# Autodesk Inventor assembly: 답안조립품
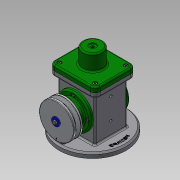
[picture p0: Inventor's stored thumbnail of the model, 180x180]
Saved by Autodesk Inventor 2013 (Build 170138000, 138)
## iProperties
Created: 2019-08
Part Number: 답안조립품
Document SubType Name: Assembly
Designer: Administrator
Author: Administrator
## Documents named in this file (17)
- C:\Documents and Settings\Administrator\바탕 화면\490804V1012\답안조립품.iam
- C:\Documents and Settings\Administrator\바탕 화면\490804V1012\본체.ipt
- C:\Documents and Settings\Administrator\바탕 화면\490804V1012\편심축.ipt
- C:\Documents and Settings\Administrator\바탕 화면\490804V1012\베어링 17 x 40 x 12.ipt
- C:\Documents and Settings\Administrator\바탕 화면\490804V1012\뒤커버.ipt
- C:\Documents and Settings\Administrator\바탕 화면\490804V1012\볼트 M4 x 8.ipt
- C:\Documents and Settings\Administrator\바탕 화면\490804V1012\앞커버.ipt
- C:\Documents and Settings\Administrator\바탕 화면\490804V1012\오일 실 17 30 8.ipt
- C:\Documents and Settings\Administrator\바탕 화면\490804V1012\키 4 x 4 x 12.ipt
- C:\Documents and Settings\Administrator\바탕 화면\490804V1012\V-벨트풀리.ipt
- C:\Documents and Settings\Administrator\바탕 화면\490804V1012\와셔 4x16.ipt
- C:\Documents and Settings\Administrator\바탕 화면\490804V1012\볼트 M4 x 10.ipt
- C:\Documents and Settings\Administrator\바탕 화면\490804V1012\링크.ipt
- C:\Documents and Settings\Administrator\바탕 화면\490804V1012\클레비스 핀 6 x 22.ipt
- 클레비스 핀 6 x 22.ipt
- C:\Documents and Settings\Administrator\바탕 화면\490804V1012\슬라이더.ipt
- C:\Documents and Settings\Administrator\바탕 화면\490804V1012\덮개.ipt
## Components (1 placed, 1 different names)
1. V-벨트풀리:1
## Component patterns: 구성요소 패턴 3:2 (2 elements)
